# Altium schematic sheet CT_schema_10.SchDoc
size 519 x 434 mm
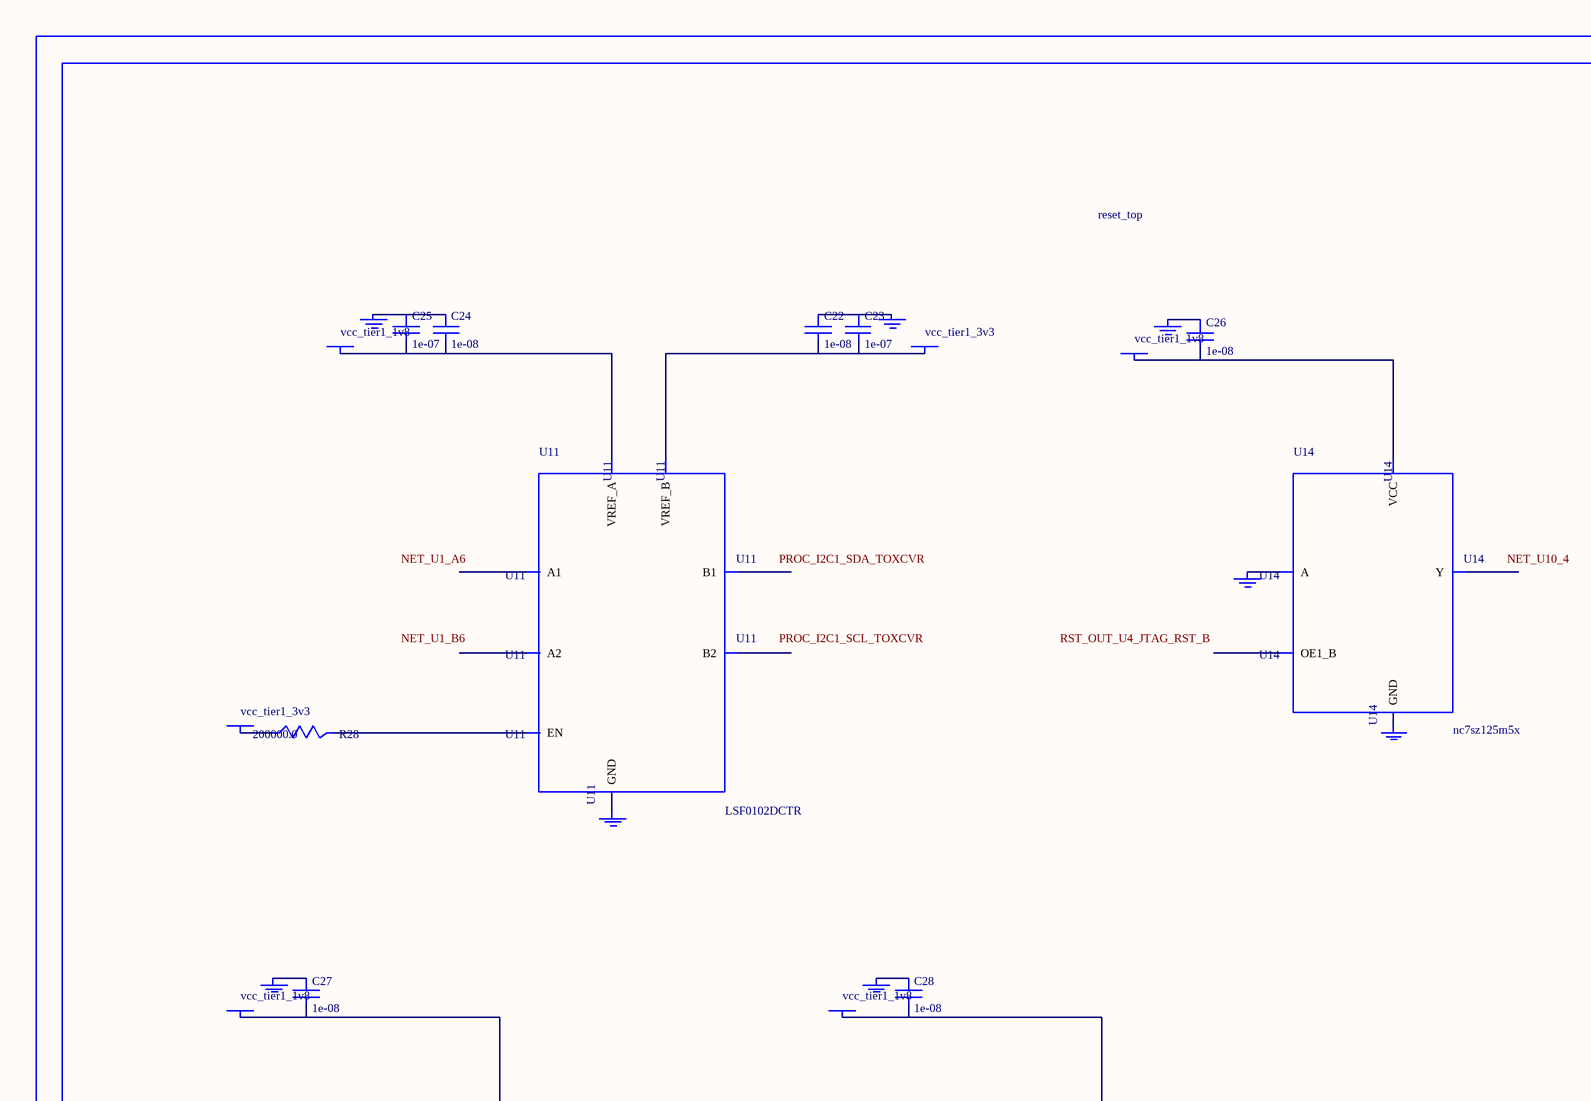
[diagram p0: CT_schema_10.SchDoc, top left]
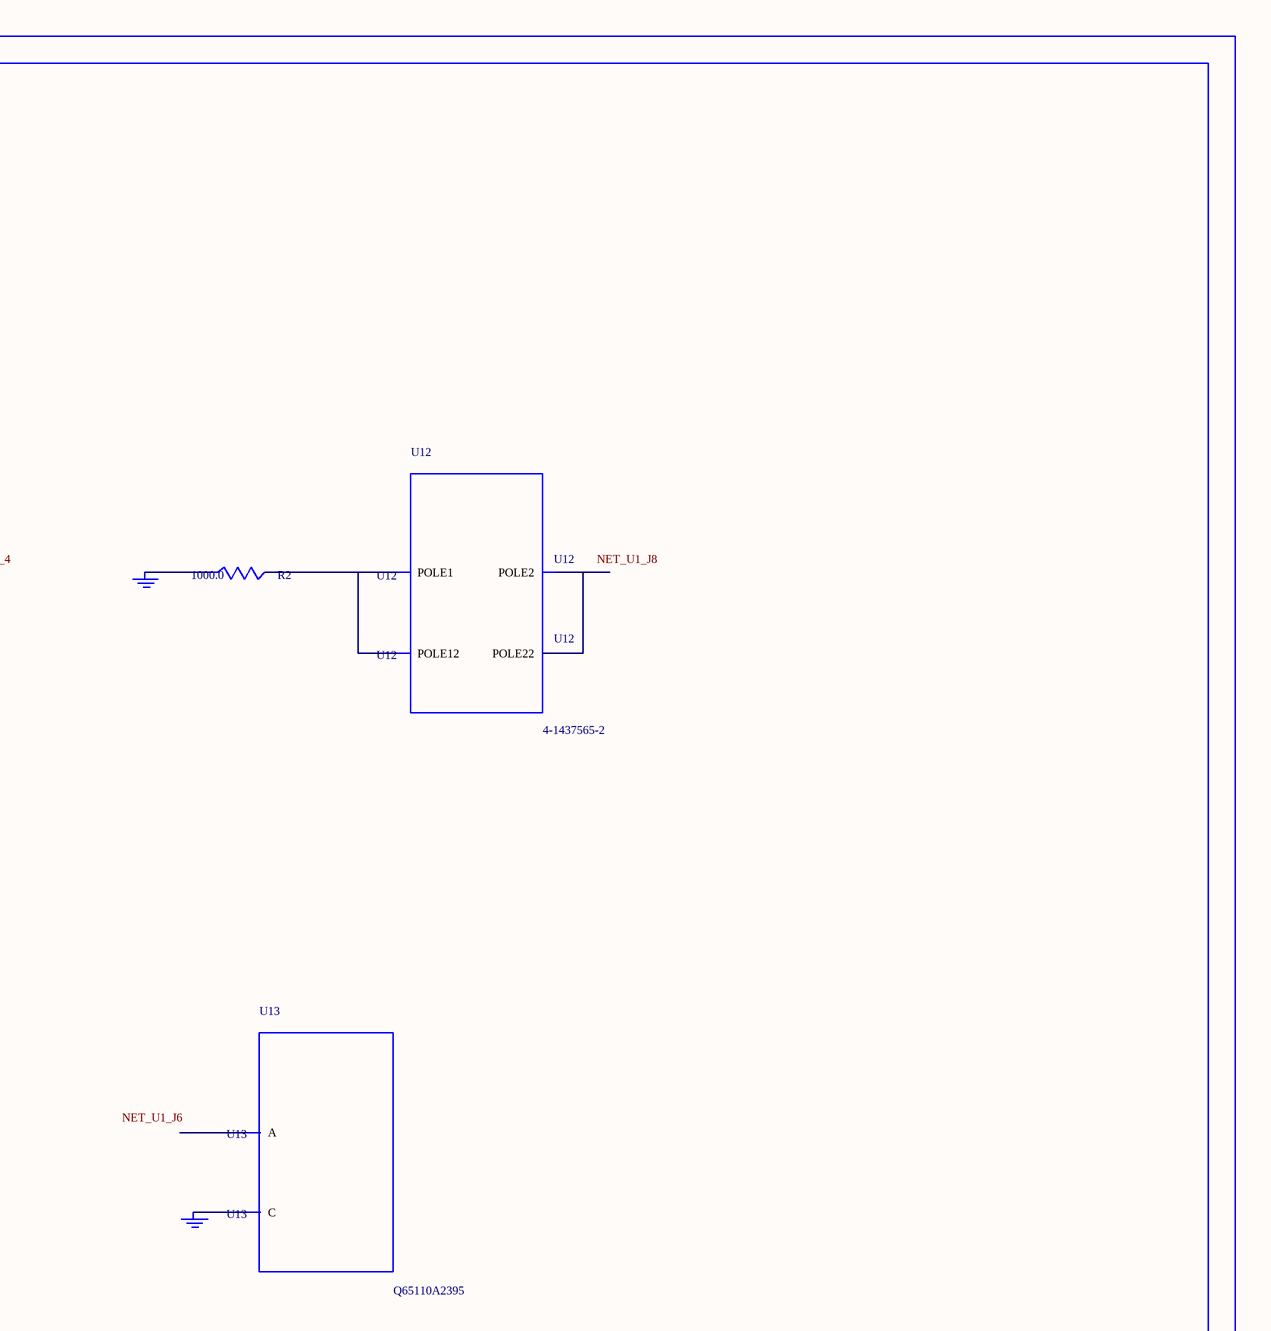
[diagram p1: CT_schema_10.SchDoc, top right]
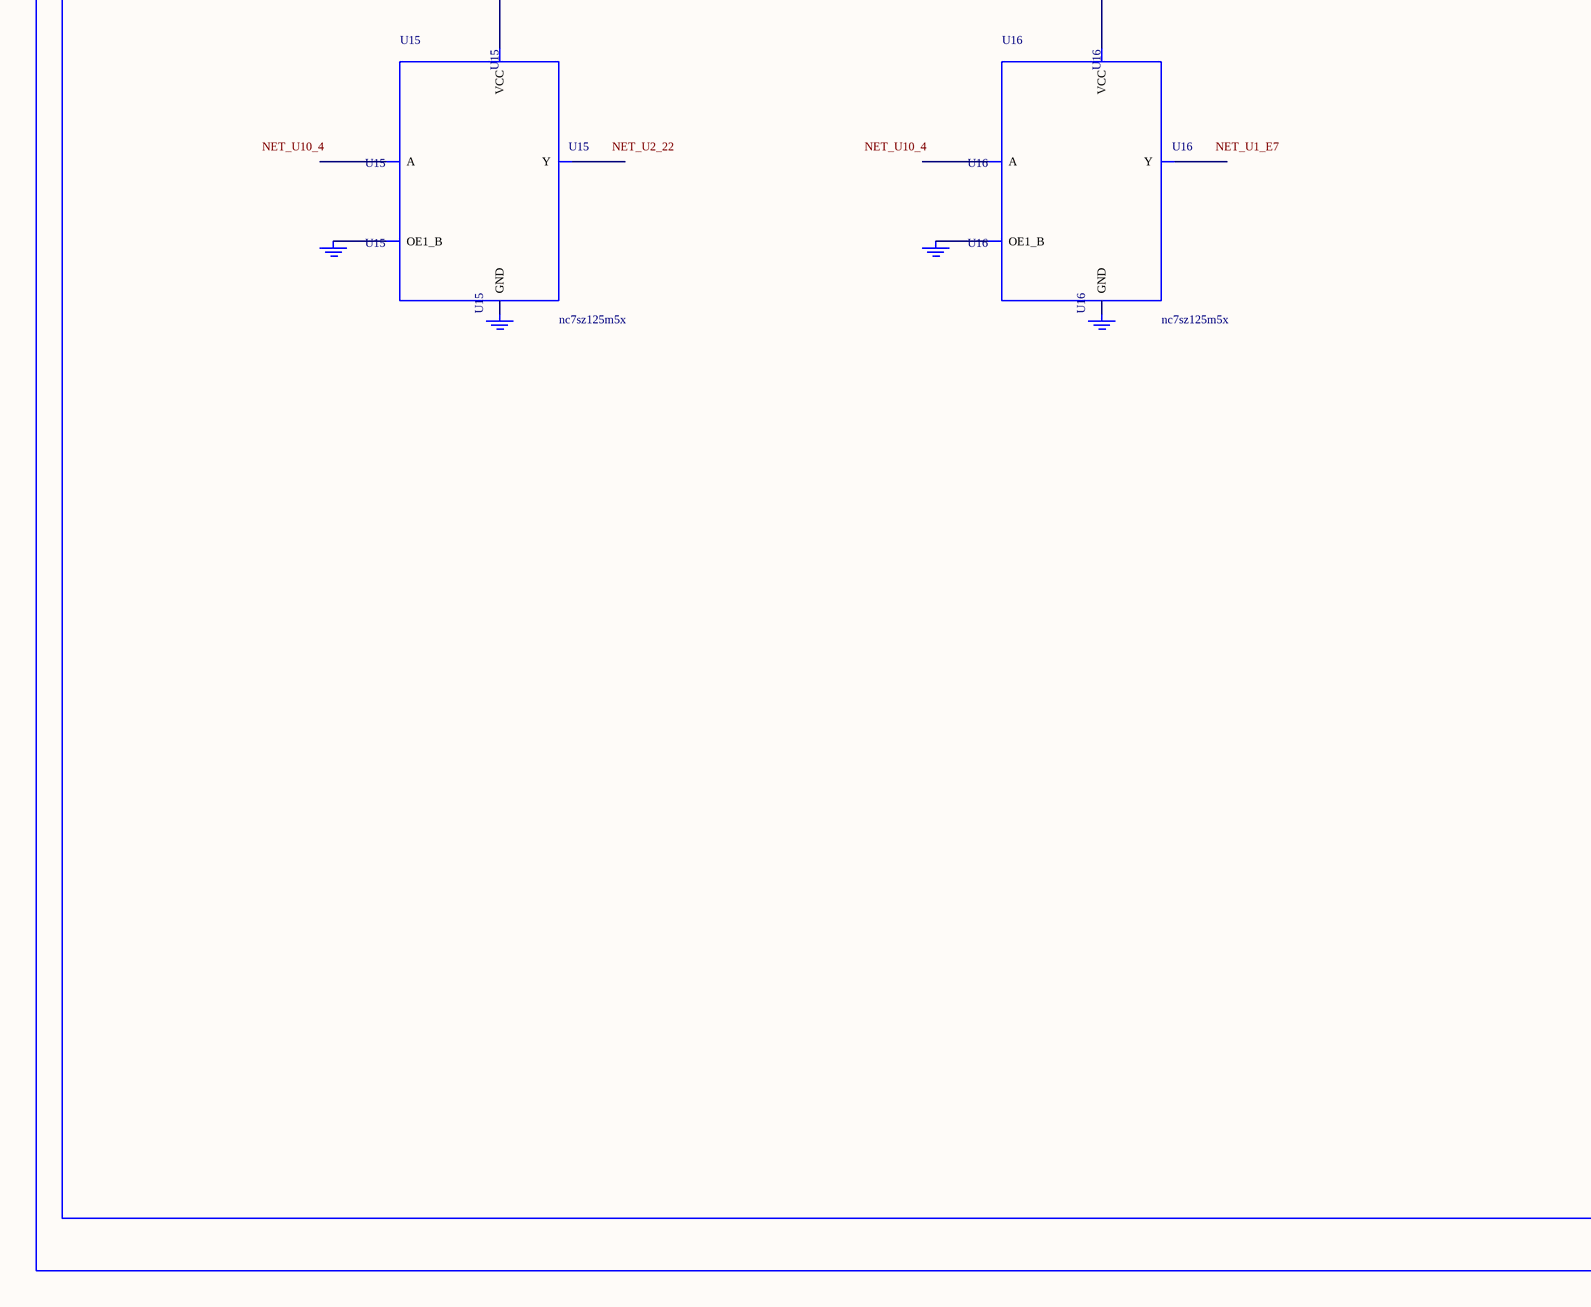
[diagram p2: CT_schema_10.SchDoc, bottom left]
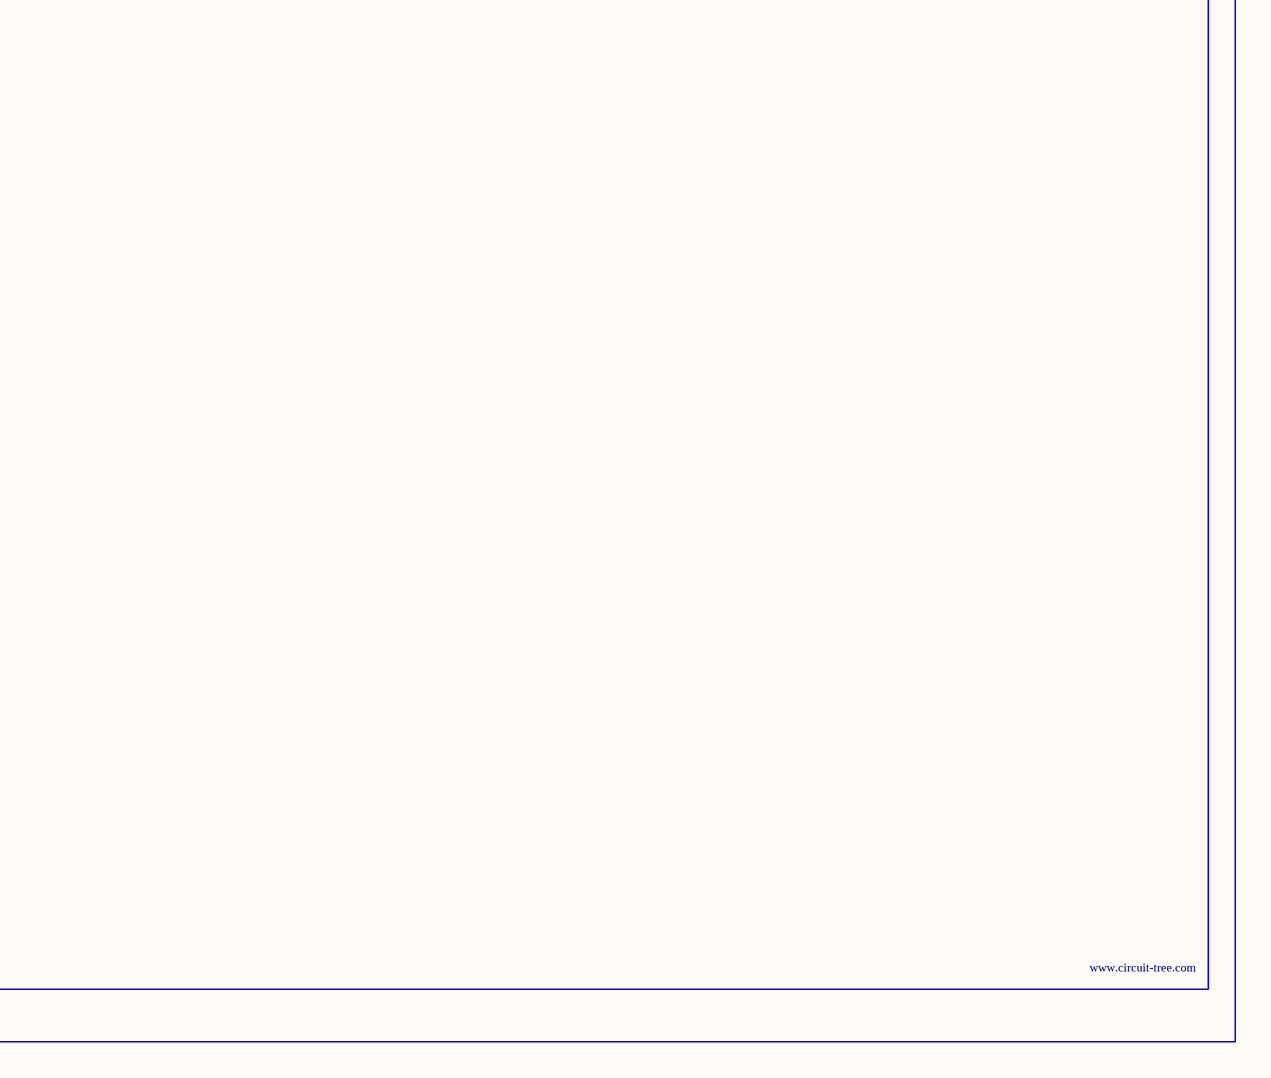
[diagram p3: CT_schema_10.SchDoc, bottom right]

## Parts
BORDER9  (no value)
C22  1e-08  [C0402]
C23  1e-07  [C0402]
C24  1e-08  [C0402]
C25  1e-07  [C0402]
C26  1e-08  [C0402]
C27  1e-08  [C0402]
C28  1e-08  [C0402]
GND_INSTANCE_9_0  (no value)
GND_INSTANCE_9_1  (no value)
GND_INSTANCE_9_2  (no value)
GND_INSTANCE_9_3  (no value)
GND_INSTANCE_9_4  (no value)
GND_INSTANCE_9_5  (no value)
GND_INSTANCE_9_6  (no value)
GND_INSTANCE_9_7  (no value)
GND_INSTANCE_9_8  (no value)
GND_INSTANCE_9_9  (no value)
GND_INSTANCE_9_10  (no value)
GND_INSTANCE_9_11  (no value)
GND_INSTANCE_9_12  (no value)
GND_INSTANCE_9_13  (no value)
POWER_INSTANCE_9_0  vcc_tier1_1v8
POWER_INSTANCE_9_1  vcc_tier1_3v3
POWER_INSTANCE_9_2  vcc_tier1_3v3
POWER_INSTANCE_9_3  vcc_tier1_1v8
POWER_INSTANCE_9_4  vcc_tier1_1v8
POWER_INSTANCE_9_5  vcc_tier1_1v8
R2  1000.0  [R0603]
R28  200000.0  [R0603]
U11  LSF0102DCTR  [DCU0008A_N]
U12  4-1437565-2  [SW_4-1437565-2]
U13  Q65110A2395  [LGM67K-G1J2-24-Z]
U14  nc7sz125m5x  [NC7SZ125M5X]
U15  nc7sz125m5x  [NC7SZ125M5X]
U16  nc7sz125m5x  [NC7SZ125M5X]

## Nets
NetC22_1: C22.1 C23.1 GND_INSTANCE_9_1.0(GND)
NetC22_2: C22.2 C23.2 POWER_INSTANCE_9_1.0(PWR) U11.7(VREF_B)
NetC24_1: C24.1 C25.1 GND_INSTANCE_9_0.0(GND)
NetC24_2: C24.2 C25.2 POWER_INSTANCE_9_0.0(PWR) U11.2(VREF_A)
NetC26_1: C26.1 GND_INSTANCE_9_5.0(GND)
NetC26_2: C26.2 POWER_INSTANCE_9_3.0(PWR) U14.5(VCC)
NetC27_1: C27.1 GND_INSTANCE_9_8.0(GND)
NetC27_2: C27.2 POWER_INSTANCE_9_4.0(PWR) U15.5(VCC)
NetC28_1: C28.1 GND_INSTANCE_9_11.0(GND)
NetC28_2: C28.2 POWER_INSTANCE_9_5.0(PWR) U16.5(VCC)
NetGND_INSTANCE_9_2_0: GND_INSTANCE_9_2.0(GND) U11.1(GND)
NetGND_INSTANCE_9_3_0: GND_INSTANCE_9_3.0(GND) R2.1
NetGND_INSTANCE_9_4_0: GND_INSTANCE_9_4.0(GND) U13.C
NetGND_INSTANCE_9_6_0: GND_INSTANCE_9_6.0(GND) U14.2(A)
NetGND_INSTANCE_9_7_0: GND_INSTANCE_9_7.0(GND) U14.3(GND)
NetGND_INSTANCE_9_9_0: GND_INSTANCE_9_9.0(GND) U15.1(OE1_B)
NetGND_INSTANCE_9_10_0: GND_INSTANCE_9_10.0(GND) U15.3(GND)
NetGND_INSTANCE_9_12_0: GND_INSTANCE_9_12.0(GND) U16.1(OE1_B)
NetGND_INSTANCE_9_13_0: GND_INSTANCE_9_13.0(GND) U16.3(GND)
NetPOWER_INSTANCE_9_2_0: POWER_INSTANCE_9_2.0(PWR) R28.1
NetR2_2: R2.2 U12.1(POLE1) U12.2(POLE12)
NetR28_2: R28.2 U11.8(EN)
NetU12_3: U12.3(POLE2) U12.4(POLE22)

Not connected (* = marked no-connect by the designer): U11 3(A1) 4(A2) 5(B2) 6(B1); U13 A; U14 1(OE1_B) 4(Y); U15 2(A) 4(Y); U16 2(A) 4(Y)

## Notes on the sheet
- Labels drawn without touching a wire or pin: NET_U1_A6, NET_U1_B6, NET_U1_E7, NET_U1_J6, NET_U1_J8, NET_U2_22, NET_U10_4, PROC_I2C1_SCL_TOXCVR, PROC_I2C1_SDA_TOXCVR, RST_OUT_U4_JTAG_RST_B

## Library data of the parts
BORDER9 = BORDER_PAGE9
C22 C24 C26-C28 = C0402C103K3RAC
C23 C25 = C0402C104K3RACTU
GND_INSTANCE_9_0-GND_INSTANCE_9_13 = GND
POWER_INSTANCE_9_0-POWER_INSTANCE_9_5 = PWR
R2 = RC0603JR-071KL
R28 = RC0603JR-07200KL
